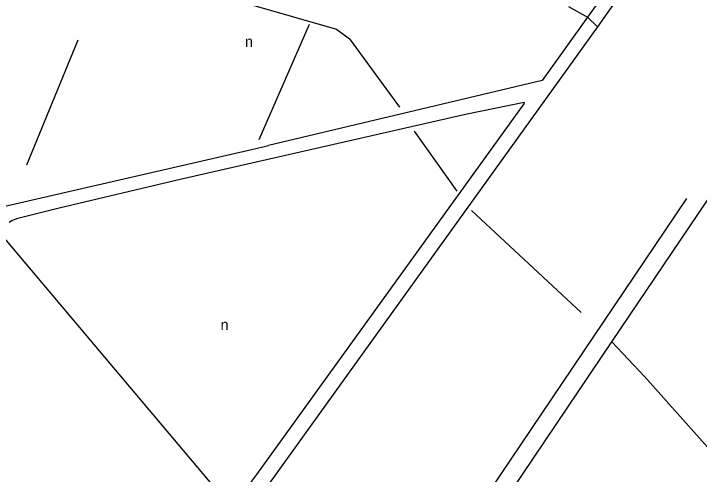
# Model space of a CAD drawing. Extents: x 158142 to 159655, y 385262 to 387204.
# Drawn here: x 158802.8 to 159056.3, y 385994 to 386164.4 of the extents above; entities that cross this region are included whole.
import ezdxf

# ---------------------------------------------------------------- set-up
doc = ezdxf.new("R2010")
doc.units = 0
for name, color, linetype in [('BLT_Basislijn', 7, 'Continuous'), ('BLT_Centroide', 7, 'Continuous'), ('BLT_Hoogspanningsmast_en_leidingen', 7, 'Continuous'), ('BLT_Vlakafsluiter', 7, 'Continuous')]:
    doc.layers.add(name, color=color, linetype=linetype)

msp = doc.modelspace()

# ---------------------------------------------------------------- linework, layer by layer
at = {"layer": 'BLT_Basislijn'}
for p, q in [((159008.04, 386167), (159015.04, 386163.12)), ((158912.06, 386160.42), (158893.5, 386117.75)), ((158807.68, 386108.44), (158826.65, 386154.75)), ((158998.22, 386139.7), (158897.02, 386115.63)), ((158950.88, 386120.96), (158966.75, 386098.76)), ((158890.75, 386114.16), (158897.02, 386115.63)), ((159023.98, 386042.92), (159071.46, 386113.34)), ((158977.33, 385985.59), (159051.69, 386095.94)), ((158972.11, 386091.53), (159012.63, 386053.8)), ((158982.88, 385981.96), (159023.98, 386042.92))]:
    msp.add_line(p, q, dxfattribs=at)
for points in [[(158821.41, 386209.88), (158819.62, 386209.45), (158813.97, 386208.96), (158781.24, 386209.43), (158779.93, 386209.28), (158778.74, 386208.13), (158778.55, 386207.06), (158786.18, 386184.09), (158790.63, 386166.67), (158791.76, 386162.26), (158793.56, 386152.97), (158797.45, 386127.33), (158798.64, 386111.47), (158799.12, 386093), (158890.75, 386114.16)], [(158835.8, 386189.99), (158853.7, 386185.02), (158871.01, 386173.44), (158922.15, 386158.65), (158927.01, 386155.08), (158945.44, 386129.76)], [(159035.84, 386183.43), (159023.8, 386166.67), (159021.94, 386164.07), (159018.67, 386159.53)], [(159022.15, 386179.38), (159022.58, 386179.08), (159022.96, 386178.71), (159023.28, 386178.29), (159023.54, 386177.83), (159023.72, 386177.34), (159023.83, 386176.82), (159023.86, 386176.29), (159023.8, 386175.76), (159023.67, 386175.25), (159023.46, 386174.77), (159023.18, 386174.32), (159022.84, 386173.92), (159022.7, 386173.78), (159015.04, 386163.12)], [(159015.04, 386163.12), (158998.22, 386139.7)], [(159018.67, 386159.53), (158888.75, 385978.75), (158860.03, 385942.95)], [(158801.15, 386087.19), (158802.13, 386087.88), (158804.38, 386088.68), (158819.59, 386092.57), (158864.39, 386103.2), (158969.86, 386127.19), (158991.64, 386131.66), (158991.49, 386130.98), (158892.61, 385993.92), (158884.81, 385983.47)], [(159125.26, 385930.42), (159117.26, 385938.99), (159100, 385958.41), (159036.11, 386030.1), (159023.98, 386042.92)]]:
    msp.add_lwpolyline(points, dxfattribs=at)
at = {"layer": 'BLT_Hoogspanningsmast_en_leidingen'}
msp.add_line((158914.81, 385944.55), (158788.37, 386094.4), dxfattribs=at)
at = {"layer": 'BLT_Vlakafsluiter'}
msp.add_line((159015.04, 386163.12), (159018.67, 386159.53), dxfattribs=at)

# ---------------------------------------------------------------- texts
at = {"layer": 'BLT_Centroide'}
for p in [(158888.34, 386152.07), (158879.32, 386047.29)]:
    msp.add_text('n', height=4, dxfattribs=at).set_placement(p)

doc.saveas('drawing.dxf')
